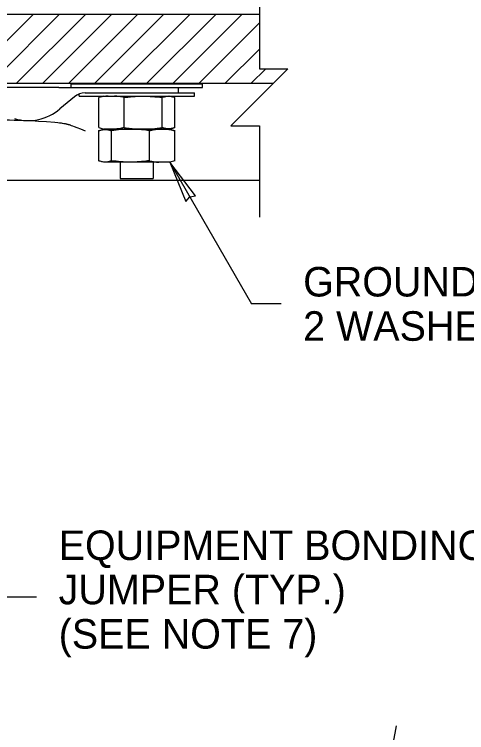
# Model space of a CAD drawing. Extents: x 99862 to 112891, y 95370 to 105076.
# Drawn here: x 100784.8 to 101030.1, y 104404.2 to 104793.4 of the extents above; entities that cross this region are included whole.
import ezdxf

# ---------------------------------------------------------------- set-up
doc = ezdxf.new("R2010")
doc.units = 0
for name, color, linetype in [('Level 11', 7, 'Continuous'), ('Level 15', 7, 'Continuous'), ('Level 2', 7, 'Continuous'), ('Level 20', 7, 'Continuous'), ('Level 22', 7, 'Continuous'), ('Level 3', 7, 'Continuous'), ('Level 4', 7, 'Continuous'), ('Level 5', 7, 'Continuous'), ('Level 9', 7, 'Continuous')]:
    doc.layers.add(name, color=color, linetype=linetype)

msp = doc.modelspace()

# ---------------------------------------------------------------- linework, layer by layer
at = {"layer": 'Level 11'}
for points in [[(100692.59, 104339.86), (100680.18, 104346.15), (100675.26, 104348.63), (100666.61, 104353.2), (100662.66, 104355.41), (100650.33, 104362.51), (100642.25, 104367.5), (100619.16, 104382.94), (100605.39, 104393.8), (100584.69, 104414.87), (100577.57, 104425.15), (100566.96, 104445.9), (100563.11, 104456.34), (100556.93, 104480.1), (100554.66, 104493.66), (100550.91, 104526.05), (100549.46, 104544.13), (100547.52, 104569.46), (100546.89, 104577.56), (100545.71, 104592.62), (100545.17, 104599.7), (100543.74, 104619.73), (100543.13, 104631.4), (100542.65, 104652.55), (100542.55, 104661.89), (100541.39, 104673.9), (100540.82, 104677.74), (100539.61, 104684.98), (100539.05, 104688.3), (100538.65, 104694.67), (100538.78, 104697.76), (100540.57, 104703.67), (100542.33, 104706.44), (100546.85, 104710.93), (100549.49, 104712.63), (100555.7, 104715.24), (100559.18, 104716.1), (100570.51, 104716.96), (100578.87, 104715.25), (100589.17, 104709.09), (100592.09, 104706.45), (100595.74, 104701.46), (100596.83, 104699.66), (100598.69, 104695.98), (100599.43, 104694.13), (100601.48, 104688.18), (100602.48, 104684.04), (100604.2, 104675.49), (100604.95, 104671.11), (100607.13, 104658.45), (100608.63, 104649.86), (100610.73, 104636.4), (100611.42, 104631.8), (100612.49, 104624.63), (100612.88, 104622.1), (100613.4, 104618.55), (100613.61, 104617), (100613.9, 104613.94), (100613.96, 104612.5), (100614.06, 104605.03), (100613.32, 104599.14), (100611.26, 104587.26), (100609.99, 104581.29), (100607.85, 104569.58), (100606.95, 104563.7), (100606.14, 104552.03), (100606.14, 104546.17), (100607.32, 104528.89), (100609.65, 104517.72), (100617.2, 104497.95), (100622.35, 104489.47), (100635.03, 104476.31), (100642.46, 104471.74), (100655.52, 104468.6), (100660.26, 104468.17), (100670.56, 104468.76), (100676.06, 104469.79), (100686.56, 104473.61), (100691.6, 104476.44), (100700.06, 104484.81), (100703.49, 104490.08), (100707.86, 104504.94), (100708.56, 104514.45), (100705.84, 104539.14), (100702.76, 104553.93), (100698.44, 104583.66), (100697.06, 104598.73), (100701.52, 104618.99), (100704.17, 104625.51), (100710.61, 104633.83), (100713.18, 104636.36), (100716.89, 104639.09), (100717.67, 104639.61), (100719.27, 104640.63), (100719.89, 104641), (100721.7, 104642.11), (100722.85, 104642.85), (100728.24, 104646.48), (100731.5, 104649.19), (100736.43, 104654.19), (100738.03, 104656.35), (100739.74, 104659.47), (100740.19, 104660.5), (100740.83, 104662.43), (100741.01, 104663.21), (100741.45, 104665.76), (100741.47, 104667.6), (100740.86, 104672.89), (100739.52, 104676.77), (100737.12, 104685.16), (100736.3, 104688.98), (100734.79, 104699.5), (100735.09, 104705.43), (100736, 104712.61), (100736.33, 104714.82), (100737.05, 104717.52), (100737.19, 104718.02), (100737.61, 104719.23), (100737.83, 104719.79), (100738.35, 104720.97), (100739, 104722.19), (100740.54, 104724.37), (100741.42, 104725.32), (100743.4, 104727.03), (100744.6, 104727.87), (100748.31, 104730.13), (100751.87, 104731.74), (100766.42, 104735.59), (100781.02, 104736.8), (100806.78, 104735.04)], [(100806.78, 104735.04), (100809.15, 104734.71), (100810.74, 104734.46), (100812.47, 104734.12), (100812.94, 104734.02), (100813.6, 104733.86), (100813.81, 104733.81), (100814.12, 104733.72), (100814, 104733.76), (100814.81, 104733.5), (100815.55, 104733.26), (100823.22, 104730.34)]]:
    msp.add_open_spline(points, degree=3, dxfattribs=at)
at = {"layer": 'Level 15'}
for p, q in [((100869.01, 104713.3), (100913.39, 104636.51)), ((100929.39, 104636.51), (100913.39, 104636.51)), ((100780.81, 104477.7), (100796.81, 104477.7))]:
    msp.add_line(p, q, dxfattribs=at)
for points in [[(100917.66, 104813.38), (100917.66, 104763.94), (100933.14, 104763.94), (100902.17, 104732.97), (100917.66, 104732.97), (100917.66, 104683.54)], [(100991.92, 104407.89), (100989.03, 104392.16), (100996.64, 104390.76), (100978.61, 104378.33), (100986.22, 104376.93), (100983.33, 104361.19)]]:
    msp.add_lwpolyline(points, dxfattribs=at)
msp.add_lwpolyline([(100869.01, 104713.3), (100877.85, 104692.04), (100879.9, 104694.45), (100883.02, 104695.02)], close=True, dxfattribs=at)
at = {"layer": 'Level 2'}
msp.add_line((100748.94, 104703.54), (100917.66, 104703.54), dxfattribs=at)
at = {"layer": 'Level 22'}
for p, q in [((100833.28, 104749.07), (100830.51, 104748.28)), ((100830.51, 104732), (100830.51, 104748.28)), ((100833.28, 104749.07), (100835.67, 104749.07)), ((100835.67, 104749.07), (100851.14, 104749.07)), ((100844.24, 104732), (100844.24, 104748.28)), ((100851.14, 104749.07), (100866.61, 104749.07)), ((100864.87, 104732), (100864.87, 104748.28)), ((100866.61, 104749.07), (100869.01, 104749.07)), ((100871.77, 104748.28), (100869.01, 104749.07)), ((100871.77, 104732), (100871.77, 104748.28)), ((100830.51, 104732), (100833.28, 104731.21)), ((100869.01, 104731.21), (100871.77, 104732)), ((100830.51, 104730.36), (100833.28, 104731.15)), ((100830.51, 104714.09), (100830.51, 104730.36)), ((100833.28, 104731.21), (100835.67, 104731.21)), ((100835.67, 104731.15), (100833.28, 104731.15)), ((100835.67, 104731.21), (100851.14, 104731.21)), ((100851.14, 104731.15), (100835.67, 104731.15)), ((100837.42, 104714.09), (100837.42, 104730.36)), ((100851.14, 104731.21), (100866.61, 104731.21)), ((100866.61, 104731.15), (100851.14, 104731.15)), ((100858.04, 104714.09), (100858.04, 104730.36)), ((100866.61, 104731.21), (100869.01, 104731.21)), ((100869.01, 104731.15), (100866.61, 104731.15)), ((100869.01, 104731.15), (100871.77, 104730.36)), ((100871.77, 104714.09), (100871.77, 104730.36)), ((100833.28, 104713.3), (100830.51, 104714.09)), ((100835.67, 104713.3), (100833.28, 104713.3)), ((100851.14, 104713.3), (100835.67, 104713.3)), ((100842.21, 104713.3), (100842.21, 104704.35)), ((100866.61, 104713.3), (100851.14, 104713.3)), ((100860.08, 104713.3), (100860.08, 104704.35)), ((100869.01, 104713.3), (100866.61, 104713.3)), ((100871.77, 104714.09), (100869.01, 104713.3)), ((100842.21, 104704.35), (100860.08, 104704.35))]:
    msp.add_line(p, q, dxfattribs=at)
for points, degree in [([(100835.67, 104749.07), (100834.81, 104749.07), (100833.09, 104748.92), (100831.37, 104748.52), (100830.51, 104748.28)], 3), ([(100830.51, 104748.28), (100830.52, 104748.28), (100830.53, 104748.28), (100830.53, 104748.28)], 2), ([(100844.24, 104748.28), (100843.38, 104748.52), (100841.66, 104748.92), (100839.95, 104749.07), (100839.09, 104749.07)], 3), ([(100844.24, 104748.28), (100845.96, 104748.52), (100847.68, 104748.72), (100851.12, 104748.99), (100852.84, 104749.07), (100854.56, 104749.07)], 3), ([(100854.56, 104749.07), (100856.28, 104749.07), (100859.72, 104748.92), (100863.16, 104748.52), (100864.87, 104748.28)], 3), ([(100868.32, 104748.97), (100868.03, 104748.94), (100866.88, 104748.79), (100865.73, 104748.52), (100864.87, 104748.28)], 3), ([(100871.77, 104748.28), (100870.91, 104748.52), (100869.76, 104748.79), (100868.61, 104748.94), (100868.32, 104748.97)], 3), ([(100830.51, 104732), (100830.52, 104732), (100830.53, 104732), (100830.53, 104732)], 2), ([(100844.24, 104732), (100843.38, 104731.76), (100841.66, 104731.36), (100839.95, 104731.21), (100839.09, 104731.21)], 3), ([(100844.24, 104732), (100845.96, 104731.76), (100847.68, 104731.56), (100851.12, 104731.28), (100852.84, 104731.21), (100854.56, 104731.21)], 3), ([(100854.56, 104731.21), (100856.28, 104731.21), (100859.72, 104731.36), (100863.16, 104731.76), (100864.87, 104732)], 3), ([(100868.32, 104731.3), (100868.03, 104731.34), (100866.88, 104731.49), (100865.73, 104731.76), (100864.87, 104732)], 3), ([(100871.77, 104732), (100870.91, 104731.76), (100869.76, 104731.49), (100868.61, 104731.33), (100868.32, 104731.3)], 3), ([(100830.51, 104730.36), (100831.37, 104730.61), (100832.52, 104730.87), (100833.67, 104731.03), (100833.96, 104731.06)], 3), ([(100830.51, 104730.36), (100830.52, 104730.36), (100830.53, 104730.36), (100830.53, 104730.36)], 2), ([(100833.96, 104731.06), (100834.25, 104731.03), (100835.41, 104730.87), (100836.56, 104730.61), (100837.42, 104730.36)], 3), ([(100847.73, 104731.15), (100846.01, 104731.15), (100842.57, 104731), (100839.13, 104730.6), (100837.42, 104730.36)], 3), ([(100858.04, 104730.36), (100856.33, 104730.6), (100854.6, 104730.8), (100851.16, 104731.08), (100849.45, 104731.15), (100847.73, 104731.15)], 3), ([(100858.04, 104730.36), (100858.9, 104730.61), (100860.62, 104731), (100862.34, 104731.15), (100863.2, 104731.15)], 3), ([(100866.61, 104731.15), (100867.47, 104731.15), (100869.19, 104731), (100870.91, 104730.61), (100871.77, 104730.36)], 3), ([(100830.51, 104714.09), (100831.37, 104713.84), (100832.52, 104713.57), (100833.67, 104713.42), (100833.96, 104713.39)], 3), ([(100833.96, 104713.39), (100834.25, 104713.42), (100835.41, 104713.57), (100836.56, 104713.84), (100837.42, 104714.09)], 3), ([(100847.73, 104713.3), (100846.01, 104713.3), (100842.57, 104713.44), (100839.13, 104713.84), (100837.42, 104714.09)], 3), ([(100858.04, 104714.09), (100856.33, 104713.84), (100854.6, 104713.64), (100851.16, 104713.37), (100849.45, 104713.3), (100847.73, 104713.3)], 3), ([(100858.04, 104714.09), (100858.9, 104713.84), (100860.62, 104713.44), (100862.34, 104713.3), (100863.2, 104713.3)], 3), ([(100871.77, 104714.09), (100871.77, 104714.08), (100871.76, 104714.08), (100871.75, 104714.08)], 2)]:
    msp.add_open_spline(points, degree=degree, dxfattribs=at)
at = {"layer": 'Level 3'}
for p, q in [((100917.66, 104793.38), (100450.84, 104793.38)), ((100757.52, 104755.88), (100795.02, 104793.38)), ((100771.66, 104755.88), (100809.16, 104793.38)), ((100785.81, 104755.88), (100823.31, 104793.38)), ((100799.95, 104755.88), (100837.45, 104793.38)), ((100814.09, 104755.88), (100851.59, 104793.38)), ((100828.23, 104755.88), (100865.73, 104793.38)), ((100842.37, 104755.88), (100879.87, 104793.38)), ((100856.52, 104755.88), (100894.02, 104793.38)), ((100870.66, 104755.88), (100908.16, 104793.38)), ((100884.8, 104755.88), (100917.66, 104788.74)), ((100898.94, 104755.88), (100917.66, 104774.59)), ((100913.08, 104755.88), (100921.15, 104763.94)), ((100925.08, 104755.88), (100530.15, 104755.88))]:
    msp.add_line(p, q, dxfattribs=at)
at = {"layer": 'Level 4'}
for points in [[(100550.66, 104660.67), (100555.65, 104648.58), (100561.3, 104634.91), (100567.28, 104620.44), (100568.26, 104618.06), (100568.92, 104616.47), (100569.23, 104615.71), (100570.95, 104611.54), (100572.22, 104608.19), (100575.82, 104598.12), (100577.92, 104591.38), (100583.74, 104571.18), (100587, 104557.78), (100591.68, 104541.54), (100592.64, 104538.32), (100593.72, 104534.93), (100593.78, 104534.73), (100593.91, 104534.34), (100593.97, 104534.15), (100594.18, 104533.48), (100594.6, 104532.13), (100595, 104530.78), (100595.77, 104528.07), (100596.24, 104526.27), (100598.5, 104517.27), (100599.96, 104510.15), (100603.58, 104497.19), (100605.73, 104491.41), (100609.99, 104484.5), (100611.56, 104482.48), (100613.84, 104480.27), (100614.31, 104479.85), (100615.04, 104479.23), (100615.41, 104478.93), (100615.79, 104478.63), (100616.05, 104478.44), (100616.16, 104478.35), (100617.7, 104477.23), (100619.07, 104476.24), (100631.51, 104467.52), (100643.06, 104460.68), (100660.73, 104450.42), (100666.67, 104446.99), (100675.6, 104441.68), (100678.58, 104439.88), (100684.54, 104436.19), (100687.44, 104434.35), (100701.99, 104425.17), (100713.54, 104417.78), (100730.92, 104406.75), (100738.18, 104402.16), (100745.46, 104397.6), (100748.38, 104395.78), (100749.82, 104394.88), (100754.28, 104392.11), (100757.26, 104390.23), (100772.28, 104380.8), (100784.58, 104373.13), (100809.24, 104360.8), (100821.57, 104356.19), (100839.55, 104353.59), (100845.46, 104353.42), (100852.07, 104354.19), (100852.99, 104354.31), (100853.9, 104354.46), (100854.27, 104354.52), (100854.49, 104354.55), (100855.12, 104354.66), (100857.24, 104355.01), (100862.75, 104355.92), (100906.74, 104363.16), (100949.03, 104370.13), (100989.46, 104394.53)], [(100535.72, 104652.11), (100540.43, 104640.71), (100545.8, 104627.71), (100551.16, 104614.72), (100552.15, 104612.34), (100552.49, 104611.52), (100552.97, 104610.35), (100553.13, 104609.97), (100553.37, 104609.38), (100553.45, 104609.18), (100553.62, 104608.78), (100553.71, 104608.56), (100555.04, 104605.32), (100556.22, 104602.22), (100559.58, 104592.82), (100561.57, 104586.43), (100567.2, 104566.9), (100570.46, 104553.51), (100574.82, 104538.38), (100575.56, 104535.86), (100576.33, 104533.34), (100576.85, 104531.66), (100577.11, 104530.83), (100577.44, 104529.76), (100577.51, 104529.55), (100577.61, 104529.24), (100577.64, 104529.15), (100577.69, 104528.98), (100577.72, 104528.91), (100577.89, 104528.35), (100578.02, 104527.94), (100578.24, 104527.23), (100578.35, 104526.85), (100578.52, 104526.25), (100578.61, 104525.94), (100578.71, 104525.61), (100578.77, 104525.39), (100578.81, 104525.27), (100579.28, 104523.61), (100579.71, 104522), (100580.97, 104516.95), (100581.77, 104513.46), (100583.44, 104506.35), (100584.3, 104502.74), (100586.34, 104495.42), (100587.5, 104491.81), (100589.6, 104486.49), (100590.36, 104484.73), (100591.63, 104482.13), (100592.08, 104481.26), (100593.01, 104479.55), (100593.51, 104478.68), (100596.08, 104474.52), (100598.53, 104471.33), (100601.85, 104468.11), (100602.23, 104467.75), (100603.02, 104467.04), (100603.44, 104466.67), (100604.27, 104465.98), (100604.64, 104465.68), (100605.04, 104465.37), (100605.17, 104465.26), (100605.33, 104465.14), (100605.41, 104465.08), (100605.46, 104465.04), (100605.47, 104465.04), (100605.66, 104464.89), (100605.81, 104464.78), (100606.05, 104464.6), (100606.13, 104464.53), (100607.7, 104463.38), (100609.18, 104462.33), (100622.42, 104453.04), (100634.41, 104445.96), (100652.19, 104435.63), (100658.08, 104432.23), (100665.35, 104427.91), (100666.8, 104427.04), (100669.69, 104425.29), (100671.12, 104424.42), (100675.46, 104421.73), (100678.33, 104419.91), (100687.02, 104414.42), (100692.81, 104410.75), (100704.38, 104403.39), (100710.19, 104399.69), (100721.78, 104392.34), (100727.61, 104388.64), (100736.41, 104383.12), (100739.36, 104381.28), (100745.21, 104377.64), (100748.17, 104375.78), (100757.2, 104370.11), (100763.4, 104366.22), (100776.1, 104358.68), (100782.6, 104355.03), (100795.95, 104348.35), (100802.76, 104345.37), (100813.21, 104341.71), (100816.73, 104340.63), (100823.86, 104338.82), (100827.48, 104338.08), (100838.38, 104336.5), (100845.81, 104336.27), (100854.24, 104337.25), (100855.18, 104337.38), (100856.37, 104337.56), (100856.59, 104337.6), (100857.02, 104337.67), (100857.26, 104337.7), (100857.9, 104337.81), (100858.32, 104337.88), (100860.44, 104338.23), (100862.14, 104338.51), (100867.23, 104339.35), (100907.33, 104345.95), (100947.44, 104352.56), (100985.79, 104374.56)], [(100982.84, 104280.62), (100979.05, 104280.65), (100975.3, 104280.7), (100951.51, 104281.24), (100932.16, 104282.43), (100893.97, 104285.87), (100874.91, 104288.14), (100837.78, 104293.26), (100819.94, 104296.08), (100788.41, 104301.55), (100775.12, 104304.07), (100751.9, 104309.29), (100741.62, 104312.09), (100720.25, 104319.24), (100708.96, 104323.62), (100684.91, 104334.2), (100672.36, 104340.32), (100635.09, 104360.88), (100610.83, 104377.29), (100584.96, 104401.72), (100578.07, 104409.88), (100567.28, 104426.13), (100563.32, 104434.17), (100553.3, 104458.76), (100549.28, 104476.38), (100543.35, 104523.37), (100541.45, 104551.63), (100539.33, 104578.54), (100539.02, 104582.45), (100538.73, 104586.25)], [(100553.46, 104586.25), (100554.01, 104579.32), (100554.6, 104571.96), (100557.09, 104539.54), (100559.21, 104511.27), (100565.75, 104469.71), (100570.1, 104454.63), (100580.67, 104432.52), (100584.96, 104425.39), (100596.62, 104410.82), (100604.17, 104403.3), (100632.33, 104380.13), (100657.28, 104364.6), (100693.67, 104346.3), (100705.7, 104340.94), (100728.14, 104332.01), (100738.15, 104328.56), (100758.59, 104322.76), (100769.22, 104320.34), (100795.25, 104315.24), (100811.03, 104312.45), (100845.7, 104306.96), (100864.53, 104304.28), (100902.33, 104299.79), (100921.18, 104297.99), (100954.45, 104295.95), (100968.67, 104295.43), (100987.97, 104295.31)]]:
    msp.add_open_spline(points, degree=3, dxfattribs=at)
at = {"layer": 'Level 5'}
for p, q in [((100804.16, 104753.68), (100757.35, 104753.68)), ((100804.11, 104753.69), (100803.98, 104753.67)), ((100808.85, 104753.68), (100804.07, 104753.68)), ((100804.16, 104753.68), (100804.16, 104753.68)), ((100804.16, 104753.68), (100804.16, 104753.68)), ((100873.84, 104750.85), (100873.84, 104753.68)), ((100817.39, 104748.75), (100809.49, 104742.11)), ((100823.14, 104750.85), (100873.84, 104750.85)), ((100882.41, 104750.85), (100882.41, 104750.85)), ((100806.24, 104739.37), (100806.24, 104739.37))]:
    msp.add_line(p, q, dxfattribs=at)
for centre, radius, start, end in [((100823.14, 104741.92), 8.93, 90, 130.0847), ((100792.24, 104762.61), 26.8, 253.809, 310.0847)]:
    msp.add_arc(centre, radius, start, end, dxfattribs=at)
msp.add_ellipse((100804.72, 104744.75), major_axis=(-0.65, 8.93), ratio=0.363443, start_param=6.25672, end_param=6.279689, dxfattribs=at)
msp.add_open_spline([(100808.85, 104753.68), (100809.33, 104753.68), (100810.35, 104753.68), (100812.49, 104753.68), (100814.22, 104753.68), (100815.39, 104753.68), (100815.41, 104753.68)], degree=3, dxfattribs=at)
at = {"layer": 'Level 9'}
for p, q in [((100815.41, 104755.65), (100864.54, 104755.65)), ((100815.41, 104755.65), (100815.41, 104753.68)), ((100864.54, 104755.65), (100886.87, 104755.65)), ((100886.87, 104753.68), (100886.87, 104755.65)), ((100815.41, 104753.68), (100860.08, 104753.68)), ((100860.08, 104753.68), (100886.87, 104753.68)), ((100819.88, 104749.13), (100819.88, 104750.24)), ((100819.88, 104749.13), (100882.41, 104749.13)), ((100873.84, 104750.85), (100882.41, 104750.85)), ((100882.41, 104750.85), (100882.41, 104750.85)), ((100882.41, 104749.13), (100882.41, 104750.85)), ((100882.41, 104749.13), (100882.41, 104749.13))]:
    msp.add_line(p, q, dxfattribs=at)

# ---------------------------------------------------------------- texts
at = {"layer": 'Level 20'}
for s, p in [('GROUND STUD WITH 2 NUTS AND', (100941.39, 104640.51)), ('2 WASHERS (TYP.) ', (100941.39, 104616.51)), ('EQUIPMENT BONDING ', (100808.81, 104497.7)), ('JUMPER (TYP.)', (100808.81, 104473.7)), ('(SEE NOTE 7)', (100808.81, 104449.7))]:
    msp.add_text(s, height=16, dxfattribs=at).set_placement(p)

doc.saveas('drawing.dxf')
